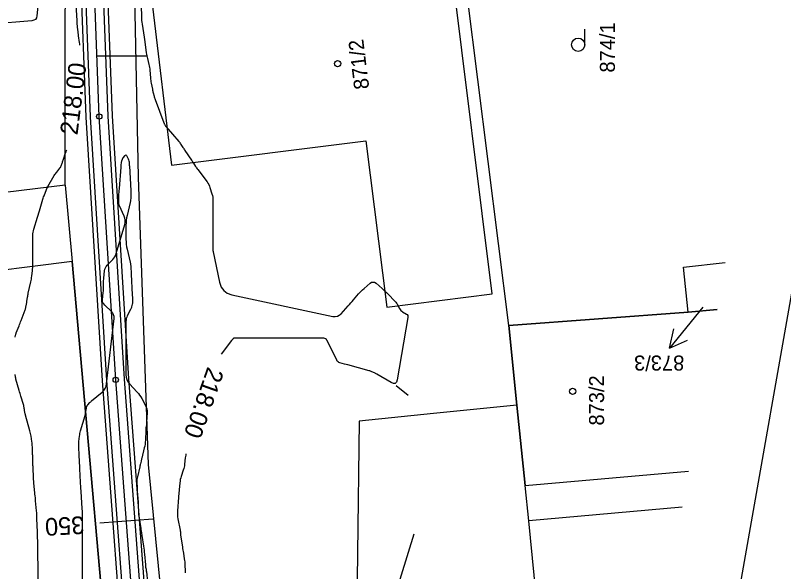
# Model space of a CAD drawing. Extents: x -534481 to -534256, y -1190577 to -1190138.
# Drawn here: x -534350.01 to -534306.48, y -1190218.06 to -1190186.56 of the extents above; entities that cross this region are included whole.
import ezdxf

# ---------------------------------------------------------------- set-up
doc = ezdxf.new("R2010")
doc.units = 0
for name, color, linetype in [('0_kroužky', 7, 'Continuous'), ('30', 7, 'Continuous'), ('31', 7, 'Continuous'), ('40', 7, 'Continuous'), ('_N_osa', 7, 'Continuous'), ('_N_text', 7, 'Continuous'), ('_rozpiska', 7, 'Continuous'), ('_tenka', 7, 'Continuous'), ('Hranice parcel', 7, 'Continuous'), ('Parcelní čísla', 7, 'Continuous'), ('Polygon budovy', 7, 'Continuous'), ('Pop  PČ popisy', 7, 'Continuous'), ('Značky budov', 7, 'Continuous'), ('Značky kultur', 7, 'Continuous')]:
    doc.layers.add(name, color=color, linetype=linetype)

msp = doc.modelspace()

# ---------------------------------------------------------------- linework, layer by layer
at = {"layer": '0_kroužky'}
for centre in [(-534345.257, -1190192.285), (-534345.257, -1190192.285), (-534345.257, -1190192.285), (-534345.257, -1190192.285), (-534345.257, -1190192.285), (-534345.257, -1190192.285), (-534344.323, -1190207.198), (-534344.323, -1190207.198), (-534344.323, -1190207.198), (-534344.323, -1190207.198), (-534344.323, -1190207.198), (-534344.323, -1190207.198)]:
    msp.add_circle(centre, 0.15, dxfattribs=at)
at = {"layer": '30'}
for points in [[(-534346.351, -1190188.242), (-534346.351, -1190188.239), (-534346.361, -1190188.163), (-534346.372, -1190188.088), (-534346.427, -1190187.725), (-534346.439, -1190187.64), (-534346.45, -1190187.554), (-534346.46, -1190187.468), (-534346.468, -1190187.382), (-534346.499, -1190187.022), (-534346.506, -1190186.933), (-534346.512, -1190186.844), (-534346.517, -1190186.755), (-534346.521, -1190186.667), (-534346.539, -1190186.147)], [(-534342.876, -1190186.046), (-534342.872, -1190186.628), (-534342.869, -1190186.736), (-534342.862, -1190186.844), (-534342.85, -1190186.951), (-534342.833, -1190187.058), (-534342.707, -1190187.785), (-534342.706, -1190187.795), (-534342.704, -1190187.805), (-534342.703, -1190187.815), (-534342.703, -1190187.826), (-534342.701, -1190187.867), (-534342.701, -1190187.877), (-534342.7, -1190187.887), (-534342.699, -1190187.897), (-534342.697, -1190187.908), (-534342.591, -1190188.676), (-534342.578, -1190188.76), (-534342.563, -1190188.844), (-534342.546, -1190188.927), (-534342.526, -1190189.009), (-534342.443, -1190189.338), (-534342.424, -1190189.421), (-534342.408, -1190189.504), (-534342.396, -1190189.587), (-534342.388, -1190189.672), (-534342.356, -1190190.091), (-534342.349, -1190190.167), (-534342.34, -1190190.243), (-534342.329, -1190190.319), (-534342.315, -1190190.394), (-534342.248, -1190190.747), (-534342.238, -1190190.796), (-534342.227, -1190190.844), (-534342.216, -1190190.892), (-534342.203, -1190190.94), (-534342.151, -1190191.131), (-534342.138, -1190191.179), (-534342.123, -1190191.226), (-534342.107, -1190191.273), (-534342.091, -1190191.32), (-534341.596, -1190192.638), (-534341.587, -1190192.659), (-534341.579, -1190192.681), (-534341.569, -1190192.701), (-534341.559, -1190192.722), (-534341.517, -1190192.804), (-534341.506, -1190192.824), (-534341.494, -1190192.843), (-534341.481, -1190192.861), (-534341.466, -1190192.879), (-534340.749, -1190193.707), (-534340.716, -1190193.746), (-534340.685, -1190193.786), (-534340.656, -1190193.827), (-534340.627, -1190193.869), (-534340.517, -1190194.04), (-534340.49, -1190194.083), (-534340.462, -1190194.125), (-534340.433, -1190194.167), (-534340.405, -1190194.209), (-534340.031, -1190194.757), (-534340.001, -1190194.801), (-534339.972, -1190194.845), (-534339.943, -1190194.889), (-534339.914, -1190194.933), (-534339.8, -1190195.111), (-534339.771, -1190195.156), (-534339.742, -1190195.199), (-534339.711, -1190195.242), (-534339.68, -1190195.285), (-534339.149, -1190195.992), (-534339.097, -1190196.067), (-534339.052, -1190196.147), (-534339.014, -1190196.23), (-534338.982, -1190196.316), (-534338.869, -1190196.668), (-534338.845, -1190196.757), (-534338.827, -1190196.847), (-534338.817, -1190196.938), (-534338.813, -1190197.029), (-534338.813, -1190197.792), (-534338.813, -1190197.95), (-534338.813, -1190198.612), (-534338.813, -1190198.845), (-534338.813, -1190199.077), (-534338.813, -1190199.792), (-534338.813, -1190199.88), (-534338.813, -1190199.897), (-534338.811, -1190199.914), (-534338.809, -1190199.932), (-534338.806, -1190199.949), (-534338.445, -1190201.678), (-534338.354, -1190201.943), (-534338.206, -1190202.15), (-534337.999, -1190202.299), (-534337.735, -1190202.39), (-534332.013, -1190203.605), (-534331.884, -1190203.618), (-534331.764, -1190203.597), (-534331.655, -1190203.544), (-534331.557, -1190203.458), (-534331.149, -1190203.009), (-534331.075, -1190202.927), (-534331.001, -1190202.843), (-534330.928, -1190202.759), (-534330.855, -1190202.675), (-534330.567, -1190202.335), (-534330.493, -1190202.251), (-534330.416, -1190202.171), (-534330.336, -1190202.094), (-534330.253, -1190202.021), (-534329.913, -1190201.732), (-534329.828, -1190201.678), (-534329.743, -1190201.66), (-534329.658, -1190201.678), (-534329.573, -1190201.732), (-534329.234, -1190202.021), (-534329.15, -1190202.094), (-534329.068, -1190202.17), (-534328.988, -1190202.247), (-534328.91, -1190202.326), (-534328.496, -1190202.756), (-534328.455, -1190202.801), (-534328.417, -1190202.849), (-534328.383, -1190202.9), (-534328.352, -1190202.953), (-534328.234, -1190203.169), (-534328.202, -1190203.22), (-534328.164, -1190203.265), (-534328.12, -1190203.306), (-534328.07, -1190203.34), (-534327.851, -1190203.472), (-534327.805, -1190203.508), (-534327.775, -1190203.552), (-534327.762, -1190203.603), (-534327.764, -1190203.662), (-534328.372, -1190207.198), (-534328.415, -1190207.333), (-534328.488, -1190207.405), (-534328.59, -1190207.413), (-534328.72, -1190207.359), (-534329.524, -1190206.885), (-534329.559, -1190206.865), (-534329.594, -1190206.846), (-534329.63, -1190206.827), (-534329.666, -1190206.809), (-534329.811, -1190206.739), (-534329.848, -1190206.722), (-534329.885, -1190206.708), (-534329.923, -1190206.695), (-534329.961, -1190206.683), (-534331.178, -1190206.359), (-534331.366, -1190206.309), (-534331.618, -1190206.242), (-534331.676, -1190206.22), (-534331.726, -1190206.188), (-534331.767, -1190206.145), (-534331.8, -1190206.092), (-534332.219, -1190205.237), (-534332.357, -1190204.957), (-534332.389, -1190204.908), (-534332.429, -1190204.873), (-534332.479, -1190204.852), (-534332.537, -1190204.845), (-534337.626, -1190204.845), (-534337.634, -1190204.845), (-534337.642, -1190204.848), (-534337.649, -1190204.852), (-534337.655, -1190204.858), (-534337.678, -1190204.885), (-534337.69, -1190204.898), (-534337.702, -1190204.911), (-534337.73, -1190204.94), (-534337.736, -1190204.947), (-534337.743, -1190204.955), (-534337.749, -1190204.962), (-534337.755, -1190204.97), (-534338.34, -1190205.741)], [(-534345.417, -1190188.845), (-534342.568, -1190188.845)], [(-534350.016, -1190204.784), (-534349.996, -1190204.662), (-534349.991, -1190204.632), (-534349.983, -1190204.602), (-534349.974, -1190204.573), (-534349.964, -1190204.544), (-534349.804, -1190204.14), (-534349.774, -1190204.063), (-534349.743, -1190203.986), (-534349.713, -1190203.909), (-534349.684, -1190203.832), (-534349.455, -1190203.237), (-534349.441, -1190203.2), (-534349.429, -1190203.161), (-534349.419, -1190203.122), (-534349.411, -1190203.083), (-534349.381, -1190202.924), (-534349.374, -1190202.884), (-534349.367, -1190202.844), (-534349.361, -1190202.804), (-534349.355, -1190202.765), (-534349.319, -1190202.515), (-534349.311, -1190202.46), (-534349.301, -1190202.405), (-534349.29, -1190202.351), (-534349.279, -1190202.297), (-534349.132, -1190201.651), (-534349.115, -1190201.572), (-534349.1, -1190201.492), (-534349.087, -1190201.411), (-534349.076, -1190201.33), (-534349.038, -1190201.006), (-534349.03, -1190200.925), (-534349.024, -1190200.844), (-534349.021, -1190200.763), (-534349.019, -1190200.681), (-534349.019, -1190200.19), (-534349.019, -1190199.983), (-534349.019, -1190199.637), (-534349.019, -1190199.43), (-534349.019, -1190199.025), (-534349.016, -1190198.935), (-534349.006, -1190198.846), (-534348.99, -1190198.758), (-534348.967, -1190198.671), (-534348.758, -1190197.989), (-534348.646, -1190197.622), (-534348.447, -1190196.968), (-534348.427, -1190196.907), (-534348.407, -1190196.845), (-534348.386, -1190196.784), (-534348.364, -1190196.723), (-534348.274, -1190196.48), (-534348.25, -1190196.42), (-534348.224, -1190196.361), (-534348.195, -1190196.303), (-534348.164, -1190196.247), (-534347.804, -1190195.63), (-534347.773, -1190195.579), (-534347.739, -1190195.528), (-534347.704, -1190195.48), (-534347.666, -1190195.432), (-534347.488, -1190195.214), (-534347.463, -1190195.182), (-534347.443, -1190195.148), (-534347.425, -1190195.112), (-534347.41, -1190195.075), (-534347.358, -1190194.921), (-534347.345, -1190194.883), (-534347.332, -1190194.845), (-534347.319, -1190194.806), (-534347.306, -1190194.768), (-534347.163, -1190194.351), (-534347.139, -1190194.285), (-534347.113, -1190194.22), (-534347.103, -1190194.195)], [(-534348.723, -1190218.633), (-534348.726, -1190217.87), (-534348.726, -1190217.819), (-534348.729, -1190217.09), (-534348.73, -1190216.967), (-534348.732, -1190216.845), (-534348.734, -1190216.722), (-534348.738, -1190216.599), (-534348.759, -1190215.87), (-534348.76, -1190215.852), (-534348.761, -1190215.83), (-534348.762, -1190215.817), (-534348.786, -1190215.063), (-534348.79, -1190214.954), (-534348.796, -1190214.845), (-534348.803, -1190214.735), (-534348.812, -1190214.626), (-534348.864, -1190214.044), (-534348.867, -1190214.008), (-534348.871, -1190213.972), (-534348.875, -1190213.936), (-534348.878, -1190213.9), (-534348.894, -1190213.757), (-534348.898, -1190213.721), (-534348.902, -1190213.686), (-534348.905, -1190213.65), (-534348.909, -1190213.614), (-534348.963, -1190213.027), (-534348.971, -1190212.936), (-534348.978, -1190212.844), (-534348.983, -1190212.753), (-534348.988, -1190212.661), (-534349.005, -1190212.25), (-534349.008, -1190212.181), (-534349.01, -1190212.112), (-534349.012, -1190212.043), (-534349.014, -1190211.975), (-534349.022, -1190211.7), (-534349.024, -1190211.631), (-534349.026, -1190211.562), (-534349.028, -1190211.493), (-534349.031, -1190211.425), (-534349.048, -1190210.996), (-534349.052, -1190210.921), (-534349.058, -1190210.845), (-534349.066, -1190210.769), (-534349.076, -1190210.694), (-534349.119, -1190210.393), (-534349.131, -1190210.318), (-534349.146, -1190210.243), (-534349.163, -1190210.169), (-534349.182, -1190210.096), (-534349.431, -1190209.208), (-534349.441, -1190209.172), (-534349.45, -1190209.136), (-534349.458, -1190209.1), (-534349.465, -1190209.063), (-534349.495, -1190208.896), (-534349.5, -1190208.87), (-534349.504, -1190208.844), (-534349.508, -1190208.819), (-534349.513, -1190208.793), (-534349.528, -1190208.689), (-534349.533, -1190208.664), (-534349.538, -1190208.638), (-534349.544, -1190208.613), (-534349.552, -1190208.588), (-534349.691, -1190208.133), (-534349.717, -1190208.049), (-534349.742, -1190207.965), (-534349.767, -1190207.881), (-534349.792, -1190207.796), (-534349.977, -1190207.157), (-534349.985, -1190207.126), (-534349.992, -1190207.096), (-534349.998, -1190207.065), (-534350.003, -1190207.033), (-534350.019, -1190206.907)], [(-534327.743, -1190208.078), (-534328.429, -1190207.531)], [(-534340.345, -1190211.396), (-534340.359, -1190211.466), (-534340.371, -1190211.544), (-534340.381, -1190211.624), (-534340.42, -1190211.977), (-534340.432, -1190212.062), (-534340.448, -1190212.146), (-534340.469, -1190212.229), (-534340.494, -1190212.311), (-534340.615, -1190212.67), (-534340.642, -1190212.758), (-534340.663, -1190212.847), (-534340.679, -1190212.937), (-534340.69, -1190213.028), (-534340.757, -1190213.822), (-534340.758, -1190213.838), (-534340.76, -1190213.865), (-534340.76, -1190213.869), (-534340.821, -1190214.611), (-534340.827, -1190214.728), (-534340.824, -1190214.844), (-534340.814, -1190214.959), (-534340.795, -1190215.074), (-534340.669, -1190215.721), (-534340.666, -1190215.742), (-534340.663, -1190215.763), (-534340.661, -1190215.784), (-534340.66, -1190215.805), (-534340.657, -1190215.89), (-534340.656, -1190215.911), (-534340.654, -1190215.932), (-534340.652, -1190215.953), (-534340.649, -1190215.974), (-534340.545, -1190216.678), (-534340.532, -1190216.761), (-534340.519, -1190216.844), (-534340.506, -1190216.928), (-534340.492, -1190217.011), (-534340.436, -1190217.343), (-534340.423, -1190217.426), (-534340.413, -1190217.51), (-534340.406, -1190217.594), (-534340.402, -1190217.678), (-534340.389, -1190218.042), (-534340.386, -1190218.123)], [(-534328.845, -1190220.569), (-534327.417, -1190215.923)]]:
    msp.add_lwpolyline(points, dxfattribs=at)
at = {"layer": '31'}
for points in [[(-534348.73, -1190186.044), (-534348.789, -1190186.585), (-534348.818, -1190186.7), (-534348.876, -1190186.785), (-534348.962, -1190186.84), (-534349.078, -1190186.866), (-534358.236, -1190187.618)], [(-534346.197, -1190218.715), (-534346.197, -1190215.208), (-534346.198, -1190215.026), (-534346.203, -1190214.845), (-534346.21, -1190214.663), (-534346.22, -1190214.481), (-534346.282, -1190213.529), (-534346.295, -1190213.324), (-534346.318, -1190212.981), (-534346.322, -1190212.913), (-534346.326, -1190212.844), (-534346.33, -1190212.776), (-534346.333, -1190212.707), (-534346.36, -1190212.154), (-534346.393, -1190211.494), (-534346.418, -1190210.999), (-534346.42, -1190210.922), (-534346.419, -1190210.845), (-534346.415, -1190210.768), (-534346.408, -1190210.691), (-534346.375, -1190210.383), (-534346.365, -1190210.307), (-534346.352, -1190210.231), (-534346.335, -1190210.155), (-534346.315, -1190210.081), (-534346.062, -1190209.214), (-534346.052, -1190209.178), (-534346.043, -1190209.141), (-534346.035, -1190209.105), (-534346.029, -1190209.068), (-534346.003, -1190208.895), (-534345.999, -1190208.87), (-534345.994, -1190208.845), (-534345.988, -1190208.82), (-534345.981, -1190208.796), (-534345.953, -1190208.698), (-534345.944, -1190208.674), (-534345.933, -1190208.652), (-534345.92, -1190208.631), (-534345.904, -1190208.612), (-534345.792, -1190208.49), (-534345.767, -1190208.463), (-534345.741, -1190208.438), (-534345.715, -1190208.414), (-534345.688, -1190208.39), (-534345.094, -1190207.892), (-534344.997, -1190207.795), (-534344.923, -1190207.686), (-534344.872, -1190207.564), (-534344.845, -1190207.43), (-534344.417, -1190203.727), (-534344.416, -1190203.614), (-534344.44, -1190203.51), (-534344.489, -1190203.415), (-534344.563, -1190203.33), (-534344.949, -1190202.97), (-534345.006, -1190202.903), (-534345.045, -1190202.83), (-534345.065, -1190202.75), (-534345.066, -1190202.662), (-534345.026, -1190202.25), (-534345.021, -1190202.182), (-534345.017, -1190202.115), (-534345.014, -1190202.047), (-534345.014, -1190201.98), (-534345.014, -1190201.709), (-534345.013, -1190201.642), (-534345.01, -1190201.574), (-534345.005, -1190201.507), (-534344.998, -1190201.44), (-534344.95, -1190201.027), (-534344.932, -1190200.939), (-534344.902, -1190200.857), (-534344.859, -1190200.781), (-534344.802, -1190200.712), (-534344.495, -1190200.389), (-534344.428, -1190200.31), (-534344.372, -1190200.225), (-534344.326, -1190200.134), (-534344.291, -1190200.036), (-534343.813, -1190198.403), (-534343.789, -1190198.284), (-534343.786, -1190198.166), (-534343.805, -1190198.051), (-534343.846, -1190197.936), (-534344.111, -1190197.348), (-534344.129, -1190197.3), (-534344.142, -1190197.252), (-534344.15, -1190197.202), (-534344.153, -1190197.152), (-534344.153, -1190196.94), (-534344.153, -1190196.892), (-534344.151, -1190196.845), (-534344.149, -1190196.797), (-534344.145, -1190196.75), (-534344.127, -1190196.512), (-534344.115, -1190196.37), (-534344.018, -1190195.15), (-534344.009, -1190195.048), (-534343.997, -1190194.894), (-534343.994, -1190194.869), (-534343.99, -1190194.845), (-534343.984, -1190194.821), (-534343.977, -1190194.798), (-534343.945, -1190194.705), (-534343.936, -1190194.682), (-534343.925, -1190194.661), (-534343.912, -1190194.64), (-534343.898, -1190194.621), (-534343.79, -1190194.491), (-534343.767, -1190194.47), (-534343.747, -1190194.465), (-534343.728, -1190194.475), (-534343.712, -1190194.501), (-534343.626, -1190194.68), (-534343.619, -1190194.696), (-534343.611, -1190194.712), (-534343.605, -1190194.729), (-534343.598, -1190194.745), (-534343.573, -1190194.811), (-534343.568, -1190194.828), (-534343.564, -1190194.845), (-534343.561, -1190194.862), (-534343.56, -1190194.88), (-534343.556, -1190194.986), (-534343.555, -1190195.009), (-534343.554, -1190195.033), (-534343.553, -1190195.056), (-534343.552, -1190195.08), (-534343.471, -1190196.5), (-534343.469, -1190196.534), (-534343.468, -1190196.569), (-534343.466, -1190196.603), (-534343.465, -1190196.638), (-534343.461, -1190196.781), (-534343.46, -1190196.813), (-534343.461, -1190196.844), (-534343.463, -1190196.876), (-534343.467, -1190196.908), (-534343.482, -1190197.034), (-534343.486, -1190197.066), (-534343.492, -1190197.097), (-534343.498, -1190197.129), (-534343.505, -1190197.16), (-534343.68, -1190197.897), (-534343.707, -1190198.031), (-534343.727, -1190198.165), (-534343.739, -1190198.301), (-534343.743, -1190198.437), (-534343.743, -1190199.254), (-534343.739, -1190199.391), (-534343.727, -1190199.526), (-534343.708, -1190199.661), (-534343.68, -1190199.794), (-534343.506, -1190200.532), (-534343.5, -1190200.563), (-534343.494, -1190200.594), (-534343.489, -1190200.625), (-534343.484, -1190200.656), (-534343.47, -1190200.782), (-534343.466, -1190200.813), (-534343.463, -1190200.845), (-534343.461, -1190200.876), (-534343.46, -1190200.908), (-534343.455, -1190201.062), (-534343.454, -1190201.098), (-534343.453, -1190201.135), (-534343.451, -1190201.171), (-534343.449, -1190201.207), (-534343.385, -1190202.391), (-534343.383, -1190202.436), (-534343.381, -1190202.482), (-534343.379, -1190202.527), (-534343.377, -1190202.572), (-534343.372, -1190202.767), (-534343.372, -1190202.806), (-534343.374, -1190202.844), (-534343.379, -1190202.882), (-534343.387, -1190202.92), (-534343.423, -1190203.071), (-534343.433, -1190203.108), (-534343.445, -1190203.145), (-534343.46, -1190203.181), (-534343.477, -1190203.215), (-534343.668, -1190203.582), (-534343.701, -1190203.655), (-534343.724, -1190203.731), (-534343.738, -1190203.81), (-534343.743, -1190203.89), (-534343.743, -1190206.916), (-534343.731, -1190207.056), (-534343.694, -1190207.186), (-534343.633, -1190207.307), (-534343.547, -1190207.419), (-534343.108, -1190207.895), (-534343.035, -1190207.979), (-534342.969, -1190208.067), (-534342.907, -1190208.159), (-534342.852, -1190208.255), (-534342.635, -1190208.661), (-534342.592, -1190208.754), (-534342.563, -1190208.851), (-534342.548, -1190208.95), (-534342.546, -1190209.052), (-534342.571, -1190209.602), (-534342.573, -1190209.639), (-534342.576, -1190209.676), (-534342.581, -1190209.712), (-534342.586, -1190209.749), (-534342.609, -1190209.894), (-534342.614, -1190209.931), (-534342.618, -1190209.967), (-534342.621, -1190210.004), (-534342.623, -1190210.041), (-534342.644, -1190210.625), (-534342.651, -1190210.734), (-534342.663, -1190210.843), (-534342.681, -1190210.951), (-534342.704, -1190211.058), (-534342.847, -1190211.642), (-534342.857, -1190211.681), (-534342.866, -1190211.721), (-534342.875, -1190211.761), (-534342.885, -1190211.801), (-534342.921, -1190211.961), (-534342.93, -1190212.001), (-534342.94, -1190212.041), (-534342.949, -1190212.081), (-534342.959, -1190212.121), (-534343.094, -1190212.691), (-534343.11, -1190212.768), (-534343.121, -1190212.846), (-534343.126, -1190212.924), (-534343.126, -1190213.003), (-534343.116, -1190213.319), (-534343.112, -1190213.398), (-534343.108, -1190213.477), (-534343.103, -1190213.556), (-534343.096, -1190213.635), (-534343.065, -1190213.983), (-534343.058, -1190214.067), (-534343.052, -1190214.151), (-534343.048, -1190214.236), (-534343.045, -1190214.32), (-534343.034, -1190214.671), (-534343.03, -1190214.758), (-534343.024, -1190214.844), (-534343.014, -1190214.93), (-534343.002, -1190215.016), (-534342.905, -1190215.628), (-534342.9, -1190215.661), (-534342.894, -1190215.693), (-534342.889, -1190215.726), (-534342.884, -1190215.758), (-534342.862, -1190215.888), (-534342.857, -1190215.92), (-534342.851, -1190215.953), (-534342.846, -1190215.985), (-534342.841, -1190216.018), (-534342.747, -1190216.623), (-534342.73, -1190216.734), (-534342.716, -1190216.845), (-534342.704, -1190216.957), (-534342.694, -1190217.068), (-534342.644, -1190217.675), (-534342.64, -1190217.707), (-534342.637, -1190217.739), (-534342.632, -1190217.772), (-534342.627, -1190217.804), (-534342.604, -1190217.931), (-534342.598, -1190217.963), (-534342.593, -1190217.996), (-534342.589, -1190218.028), (-534342.586, -1190218.06), (-534342.526, -1190218.667)]]:
    msp.add_lwpolyline(points, dxfattribs=at)
at = {"layer": '_N_osa'}
msp.add_lwpolyline([(-534342.428, -1190234.65), (-534342.865, -1190226.62), (-534344.323, -1190207.198), (-534345.257, -1190192.285), (-534345.89, -1190175.458), (-534346.05, -1190156.962), (-534344.257, -1190151.926), (-534342.463, -1190149.215)], dxfattribs=at)
at = {"layer": '_N_text'}
msp.add_lwpolyline([(-534342.226, -1190215.093), (-534345.218, -1190215.318)], dxfattribs=at)
at = {"layer": '_rozpiska'}
msp.add_line((-534313.394, -1190244.109), (-534298.633, -1190160.401), dxfattribs=at)
at = {"layer": '_tenka'}
for points in [[(-534343.317, -1190232.109), (-534343.613, -1190226.668), (-534345.072, -1190207.25), (-534346.006, -1190192.323), (-534346.64, -1190175.475), (-534346.801, -1190156.835), (-534344.933, -1190151.588), (-534343.268, -1190149.073)], [(-534343.067, -1190232.098), (-534343.364, -1190226.652), (-534344.822, -1190207.233), (-534345.756, -1190192.31), (-534346.39, -1190175.47), (-534346.551, -1190156.878), (-534344.708, -1190151.701), (-534343, -1190149.12)], [(-534342.068, -1190232.057), (-534342.366, -1190226.587), (-534343.825, -1190207.164), (-534344.757, -1190192.26), (-534345.39, -1190175.446), (-534345.55, -1190157.046), (-534343.807, -1190152.151), (-534341.926, -1190149.309)], [(-534341.818, -1190232.046), (-534342.116, -1190226.571), (-534343.575, -1190207.147), (-534344.507, -1190192.248), (-534345.14, -1190175.441), (-534345.299, -1190157.088), (-534343.581, -1190152.264), (-534341.657, -1190149.357)]]:
    msp.add_lwpolyline(points, dxfattribs=at)
at = {"layer": 'Hranice parcel'}
for p, q in [((-534322.05, -1190204.13), (-534324.69, -1190183.16)), ((-534322.05, -1190204.13), (-534311.89, -1190203.37)), ((-534311.89, -1190203.37), (-534310.251, -1190203.215)), ((-534321.59, -1190208.63), (-534322.05, -1190204.13)), ((-534312.226, -1190214.415), (-534320.92, -1190215.18))]:
    msp.add_line(p, q, dxfattribs=at)
for points in [[(-534347.19, -1190196.18), (-534347.17, -1190176.21), (-534348.39, -1190156.38), (-534345.398, -1190148.697)], [(-534340.96, -1190232.41), (-534341.05, -1190227.37), (-534341.07, -1190226.16), (-534342.47, -1190212), (-534343.03, -1190195.73), (-534343.24, -1190185.5)], [(-534347.19, -1190196.18), (-534354, -1190197), (-534354.73, -1190197.08)], [(-534347.19, -1190196.18), (-534346.8, -1190200.49), (-534345.1, -1190219.6), (-534344.81, -1190226.96), (-534344.61, -1190231.96)], [(-534311.89, -1190203.37), (-534312.15, -1190200.81), (-534309.784, -1190200.563)], [(-534321.59, -1190208.63), (-534326.31, -1190209.11), (-534330.53, -1190209.55), (-534330.71, -1190224.5), (-534330.89, -1190225.71), (-534332.08, -1190233.8)], [(-534320.92, -1190215.18), (-534321.12, -1190213.19), (-534321.59, -1190208.63)], [(-534321.41, -1190235.44), (-534320.43, -1190229.08), (-534320.03, -1190226.45), (-534319.98, -1190226.15), (-534319.89, -1190225.56), (-534320.92, -1190215.18)]]:
    msp.add_lwpolyline(points, dxfattribs=at)
at = {"layer": 'Polygon budovy'}
for points in [[(-534325.28, -1190183.96), (-534342.24, -1190186.06), (-534341.16, -1190195.04), (-534330.16, -1190193.66), (-534328.97, -1190203.08), (-534323, -1190202.33)], [(-534356.39, -1190231.73), (-534347.08, -1190231.91), (-534344.61, -1190231.96), (-534344.81, -1190226.96), (-534345.1, -1190219.6), (-534346.8, -1190200.49), (-534353.41, -1190201.32), (-534350.57, -1190219.42), (-534356.2, -1190219.31)]]:
    msp.add_lwpolyline(points, close=True, dxfattribs=at)
msp.add_lwpolyline([(-534310.251, -1190203.215), (-534311.89, -1190203.37), (-534322.05, -1190204.13), (-534321.59, -1190208.63), (-534321.12, -1190213.19), (-534311.868, -1190212.381)], dxfattribs=at)
at = {"layer": 'Pop  PČ popisy'}
for p, q in [((-534311.051, -1190203.076), (-534312.94, -1190205.408)), ((-534312.94, -1190205.408), (-534312.698, -1190204.315)), ((-534312.94, -1190205.408), (-534311.92, -1190204.945))]:
    msp.add_line(p, q, dxfattribs=at)
at = {"layer": 'Značky budov'}
for centre in [(-534331.751, -1190189.294), (-534318.435, -1190207.847)]:
    msp.add_circle(centre, 0.175, dxfattribs=at)
at = {"layer": 'Značky kultur'}
msp.add_line((-534317.741, -1190188.223), (-534317.741, -1190187.348), dxfattribs=at)
msp.add_circle((-534318.117, -1190188.223), 0.375, dxfattribs=at)

# ---------------------------------------------------------------- texts
at = {"layer": '40'}
for rotation, p in [(82.8047, (-534346.492, -1190193.367)), (250.4804, (-534339.112, -1190206.42))]:
    msp.add_text('218.00', height=1, rotation=rotation, dxfattribs=at).set_placement(p)
at = {"layer": '_N_text'}
msp.add_text('350', height=1, rotation=183.0689, dxfattribs=at).set_placement((-534346.128, -1190214.921))
at = {"layer": '_rozpiska'}
msp.add_text('STAROHORSKÝ POTOK, HLUK - ŘKM 0,000 ', height=1.2825, rotation=80, dxfattribs=at).set_placement((-534307.068, -1190232.21))
at = {"layer": 'Parcelní čísla'}
for s, rotation, p in [('874/1', 90, (-534316.038, -1190189.799)), ('871/2', 97, (-534329.954, -1190190.7)), ('873/3', 180, (-534312.104, -1190205.824)), ('873/2', 90, (-534316.651, -1190209.788))]:
    msp.add_text(s, height=0.85, rotation=rotation, dxfattribs=at).set_placement(p)

doc.saveas('drawing.dxf')
